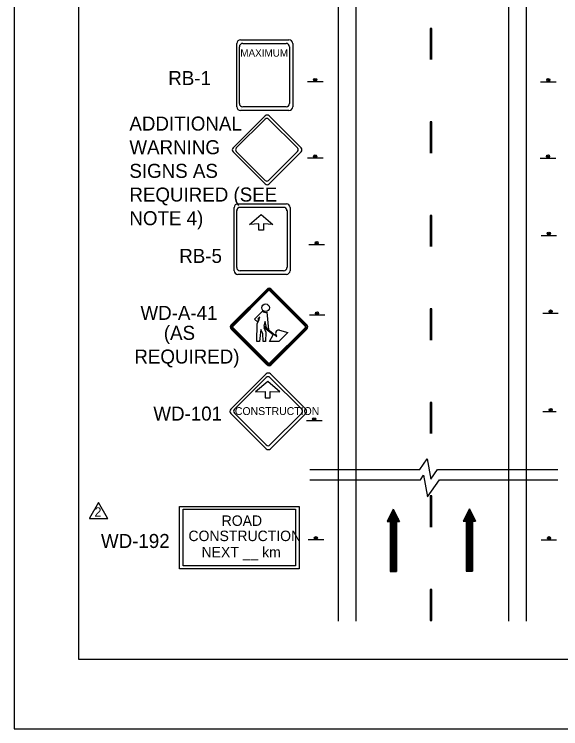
# Model space of a CAD drawing. Extents: x 1381 to 1597, y 125 to 404.
# Drawn here: x 1381.2 to 1466.1, y 124.9 to 235.9 of the extents above; entities that cross this region are included whole.
import ezdxf

# ---------------------------------------------------------------- set-up
doc = ezdxf.new("R2010")
doc.units = 0
for name, color, linetype in [('Level 1', 7, 'Continuous'), ('Level 10', 7, 'Continuous'), ('Level 2', 7, 'Continuous'), ('Level 44', 7, 'Continuous'), ('Level 60', 7, 'Continuous')]:
    doc.layers.add(name, color=color, linetype=linetype)

msp = doc.modelspace()

# ---------------------------------------------------------------- linework, layer by layer
at = {"layer": 'Level 1'}
for p, q in [((1420.46, 193.21), (1414.88, 187.63)), ((1420.58, 193.08), (1415, 187.51)), ((1426.54, 187.51), (1420.96, 193.08)), ((1426.66, 187.63), (1421.09, 193.21)), ((1420.71, 192.96), (1415.13, 187.39)), ((1426.41, 187.38), (1420.84, 192.96)), ((1420.51, 190.76), (1420.5, 190.76)), ((1414.88, 187), (1420.45, 181.43)), ((1415, 187.13), (1420.58, 181.56)), ((1415.13, 187.25), (1420.7, 181.68)), ((1420.84, 181.68), (1426.41, 187.25)), ((1420.96, 181.56), (1426.54, 187.13)), ((1421.08, 181.43), (1426.66, 187))]:
    msp.add_line(p, q, dxfattribs=at)
for points in [[(1419.05, 188.56), (1419.19, 188.44), (1419.03, 188.04), (1418.52, 188.52), (1419.74, 189.77)], [(1419.05, 188.56), (1419.19, 188.44), (1419.03, 188.04), (1418.52, 188.52), (1419.74, 189.77)], [(1419.47, 186.95), (1419.29, 185.05), (1418.86, 185.05), (1418.92, 187.78), (1419.03, 188.04), (1418.52, 188.52), (1419.74, 189.77)], [(1422.41, 186.83), (1423.69, 186.44), (1422.3, 185.05), (1420.84, 185.05), (1421.39, 186.1), (1419.98, 187.26), (1420.25, 186.52), (1420.22, 185.05), (1419.87, 185.05), (1419.81, 186.31), (1419.47, 186.95), (1419.29, 185.05), (1418.86, 185.05), (1418.92, 187.78), (1419.36, 188.88), (1419.05, 188.56)], [(1422.41, 186.83), (1423.69, 186.44), (1422.3, 185.05), (1420.84, 185.05), (1421.39, 186.1), (1419.98, 187.26), (1420.25, 186.52), (1420.22, 185.05), (1419.87, 185.05), (1419.81, 186.31), (1419.47, 186.95), (1419.29, 185.05), (1418.86, 185.05), (1418.92, 187.78), (1419.36, 188.88), (1419.05, 188.56)], [(1420.43, 189.6), (1420.71, 186.88), (1420.35, 187.18), (1420.15, 188.19), (1419.98, 187.48), (1421.96, 185.84), (1421.83, 186.2)], [(1420.43, 189.6), (1420.71, 186.88), (1420.35, 187.18), (1420.15, 188.19), (1419.98, 187.48), (1421.96, 185.84), (1421.83, 186.2)], [(1420.43, 189.6), (1420.71, 186.88), (1421.96, 185.84), (1421.83, 186.2)], [(1422.41, 186.83), (1423.69, 186.44), (1422.3, 185.05), (1420.84, 185.05), (1421.39, 186.1), (1419.98, 187.26), (1420.25, 186.52), (1420.22, 185.05), (1419.87, 185.05), (1419.81, 186.31), (1419.47, 186.95)]]:
    msp.add_lwpolyline(points, dxfattribs=at)
for points in [[(1419.05, 188.56), (1419.19, 188.44), (1419.36, 188.88)], [(1420.35, 187.17), (1420.15, 188.19), (1419.98, 187.48)]]:
    msp.add_lwpolyline(points, close=True, dxfattribs=at)
msp.add_circle((1420.24, 190.31), 0.591, dxfattribs=at)
msp.add_circle((1420.24, 190.31), 0.591, dxfattribs=at)
msp.add_circle((1420.24, 190.31), 0.591, dxfattribs=at)
for centre, radius, start, end in [((1420.77, 192.89), 0.446, 45, 134.9651), ((1420.77, 192.89), 0.27, 45, 134.9651), ((1420.77, 192.89), 0.0948, 45, 134.9651), ((1420.24, 190.31), 0.734, 226.3135, 284.9576), ((1420.24, 190.31), 0.734, 226.3135, 284.9576), ((1420.24, 190.31), 0.734, 226.3135, 284.9576), ((1415.19, 187.32), 0.446, 134.965, 225), ((1415.19, 187.32), 0.27, 134.965, 225), ((1426.35, 187.32), 0.27, 314.9651, 45), ((1426.35, 187.32), 0.446, 314.9651, 45), ((1415.19, 187.32), 0.0948, 134.965, 225), ((1422.27, 186.37), 0.475, 73.381, 201.0999), ((1422.27, 186.37), 0.475, 73.381, 201.0999), ((1422.27, 186.37), 0.475, 73.381, 201.0999), ((1426.35, 187.32), 0.0948, 314.9651, 45), ((1420.77, 181.75), 0.446, 225, 314.9652), ((1420.77, 181.75), 0.27, 225, 314.9652), ((1420.77, 181.75), 0.0948, 225, 314.9652)]:
    msp.add_arc(centre, radius, start, end, dxfattribs=at)
at = {"layer": 'Level 10'}
for p, q in [((1434.3, 141.65), (1434.3, 387.59)), ((1458.01, 141.65), (1458.01, 387.59)), ((1460.73, 387.59), (1460.73, 141.65)), ((1431.55, 141.65), (1431.55, 334.55)), ((1440.08, 159.02), (1439.11, 157.09)), ((1439.96, 158.78), (1439.96, 149.34)), ((1440.08, 159.02), (1440.08, 149.34)), ((1440.08, 159.02), (1441.05, 157.09)), ((1440.2, 158.78), (1440.2, 149.34)), ((1451.9, 159.07), (1450.93, 157.14)), ((1451.78, 158.83), (1451.78, 149.4)), ((1451.9, 159.07), (1451.9, 149.4)), ((1451.9, 159.07), (1452.86, 157.14)), ((1452.02, 158.83), (1452.02, 149.4)), ((1439.36, 157.57), (1439.36, 157.09)), ((1439.48, 157.81), (1439.48, 157.09)), ((1439.6, 158.06), (1439.6, 149.34)), ((1439.72, 158.3), (1439.72, 149.34)), ((1439.84, 158.54), (1439.84, 149.34)), ((1440.32, 158.54), (1440.32, 149.34)), ((1440.44, 158.3), (1440.44, 149.34)), ((1440.57, 158.06), (1440.57, 149.34)), ((1440.68, 157.81), (1440.68, 157.09)), ((1440.81, 157.57), (1440.81, 157.09)), ((1451.17, 157.62), (1451.17, 157.14)), ((1451.29, 157.86), (1451.29, 157.14)), ((1451.41, 158.11), (1451.41, 149.4)), ((1451.53, 158.35), (1451.53, 149.4)), ((1451.65, 158.59), (1451.65, 149.4)), ((1452.14, 158.59), (1452.14, 149.4)), ((1452.26, 158.35), (1452.26, 149.4)), ((1452.38, 158.11), (1452.38, 149.4)), ((1452.5, 157.86), (1452.5, 157.14)), ((1452.62, 157.62), (1452.62, 157.14)), ((1439.11, 157.09), (1439.6, 157.09)), ((1439.23, 157.33), (1439.23, 157.09)), ((1439.6, 157.09), (1439.6, 149.34)), ((1440.57, 157.09), (1440.57, 149.34)), ((1440.57, 157.09), (1441.05, 157.09)), ((1440.93, 157.33), (1440.93, 157.09)), ((1450.93, 157.14), (1451.41, 157.14)), ((1451.05, 157.38), (1451.05, 157.14)), ((1451.41, 157.14), (1451.41, 149.4)), ((1452.38, 157.14), (1452.38, 149.4)), ((1452.38, 157.14), (1452.86, 157.14)), ((1452.74, 157.38), (1452.74, 157.14)), ((1439.6, 149.34), (1440.57, 149.34)), ((1451.41, 149.4), (1452.38, 149.4))]:
    msp.add_line(p, q, dxfattribs=at)
at = {"layer": 'Level 2'}
for p, q in [((1445.8, 233.66), (1445.8, 228.83)), ((1446.09, 233.66), (1445.8, 233.66)), ((1446.09, 228.83), (1446.09, 233.66)), ((1445.8, 219.15), (1445.8, 214.31)), ((1446.09, 219.15), (1445.8, 219.15)), ((1446.09, 214.31), (1446.09, 219.15)), ((1445.8, 204.64), (1445.8, 199.8)), ((1446.09, 204.64), (1445.8, 204.64)), ((1446.09, 199.8), (1446.09, 204.64)), ((1445.8, 190.12), (1445.8, 185.28)), ((1446.09, 190.12), (1445.8, 190.12)), ((1446.09, 185.28), (1446.09, 190.12)), ((1445.8, 175.61), (1445.8, 170.77)), ((1446.09, 175.61), (1445.8, 175.61)), ((1446.09, 170.77), (1446.09, 175.61)), ((1445.8, 161.09), (1445.8, 156.26)), ((1446.09, 161.09), (1445.8, 161.09)), ((1446.09, 156.26), (1446.09, 161.09)), ((1445.8, 146.58), (1445.8, 141.74)), ((1446.09, 146.58), (1445.8, 146.58)), ((1446.09, 141.74), (1446.09, 146.58)), ((1445.8, 141.74), (1446.09, 141.74))]:
    msp.add_line(p, q, dxfattribs=at)
for points in [[(1406.85, 159.43), (1425.47, 159.43), (1425.47, 149.77), (1406.85, 149.77)], [(1407.43, 159.05), (1424.86, 159.05), (1424.86, 150.24), (1407.43, 150.24)]]:
    msp.add_lwpolyline(points, close=True, dxfattribs=at)
at = {"layer": 'Level 44'}
for p, q in [((1416.35, 231.89), (1423.87, 231.89)), ((1415.77, 221.52), (1415.77, 231.31)), ((1416.16, 222.01), (1416.16, 230.83)), ((1416.68, 231.35), (1423.44, 231.35)), ((1423.97, 230.83), (1423.97, 222.01)), ((1424.45, 231.31), (1424.45, 221.52)), ((1429.16, 225.4), (1426.74, 225.4)), ((1429.16, 225.4), (1426.74, 225.4)), ((1462.95, 225.4), (1465.37, 225.4)), ((1416.16, 222.01), (1416.16, 222.01)), ((1415.77, 221.51), (1415.77, 221.52)), ((1423.87, 220.93), (1416.35, 220.93)), ((1416.48, 221.17), (1416.48, 221.17)), ((1423.44, 221.49), (1416.68, 221.49)), ((1420.18, 220.1), (1415.19, 215.11)), ((1425.76, 215.11), (1420.77, 220.1)), ((1415.68, 215.11), (1420.18, 219.6)), ((1420.71, 219.6), (1425.2, 215.11)), ((1415.19, 214.52), (1420.18, 209.53)), ((1415.19, 214.52), (1415.19, 214.52)), ((1420.18, 210.08), (1415.68, 214.58)), ((1425.2, 214.58), (1420.71, 210.08)), ((1420.77, 209.53), (1425.76, 214.52)), ((1429.16, 213.54), (1426.74, 213.54)), ((1429.16, 213.54), (1426.74, 213.54)), ((1462.91, 213.53), (1465.33, 213.53)), ((1415.94, 206.44), (1423.46, 206.44)), ((1415.36, 196.06), (1415.36, 205.86)), ((1415.75, 196.56), (1415.75, 205.38)), ((1416.27, 205.9), (1423.04, 205.9)), ((1423.56, 205.38), (1423.56, 196.56)), ((1424.04, 205.86), (1424.04, 196.06)), ((1463.03, 201.54), (1465.45, 201.54)), ((1463.03, 201.54), (1465.45, 201.54)), ((1429.39, 200.07), (1426.97, 200.07)), ((1429.39, 200.07), (1426.97, 200.07)), ((1415.75, 196.55), (1415.75, 196.56)), ((1415.36, 196.06), (1415.36, 196.06)), ((1423.46, 195.48), (1415.94, 195.48)), ((1423.04, 196.03), (1416.27, 196.03)), ((1429.44, 189.15), (1427.03, 189.15)), ((1463.3, 189.46), (1465.72, 189.46)), ((1420.33, 180.03), (1414.84, 174.54)), ((1426.46, 174.54), (1420.98, 180.03)), ((1415.39, 174.53), (1420.33, 179.47)), ((1420.57, 178.83), (1418.68, 177.23)), ((1422.46, 177.23), (1420.57, 178.83)), ((1420.91, 179.47), (1425.85, 174.53)), ((1418.68, 177.23), (1420.19, 177.31)), ((1420.19, 177.31), (1420.19, 176.31)), ((1420.95, 176.31), (1420.95, 177.31)), ((1420.95, 177.31), (1422.46, 177.23)), ((1420.19, 176.31), (1420.94, 176.31)), ((1463.33, 174.17), (1465.4, 174.17)), ((1414.84, 173.89), (1420.33, 168.4)), ((1414.84, 173.89), (1414.84, 173.89)), ((1420.33, 169.01), (1415.39, 173.95)), ((1425.85, 173.95), (1420.91, 169.01)), ((1420.98, 168.4), (1426.46, 173.89)), ((1429, 172.72), (1426.58, 172.72)), ((1429, 172.72), (1426.58, 172.72)), ((1444.19, 165.21), (1445.33, 166.82)), ((1445.33, 166.82), (1445.89, 163.7)), ((1427.1, 165.21), (1444.19, 165.21)), ((1444.28, 163.59), (1444.78, 164.29)), ((1444.78, 164.29), (1445.37, 160.93)), ((1445.89, 163.7), (1446.95, 165.21)), ((1446.95, 165.21), (1465.66, 165.21)), ((1427.1, 163.59), (1444.28, 163.59)), ((1445.37, 160.93), (1447.25, 163.59)), ((1447.25, 163.59), (1465.66, 163.59)), ((1429.26, 154.25), (1426.84, 154.25)), ((1429.26, 154.25), (1426.84, 154.25)), ((1429.26, 154.25), (1426.84, 154.25)), ((1429.26, 154.25), (1426.84, 154.25)), ((1463.04, 154.25), (1465.46, 154.25))]:
    msp.add_line(p, q, dxfattribs=at)
msp.add_lwpolyline([(1417.73, 203.23), (1419.55, 204.76), (1421.36, 203.23), (1419.91, 203.31), (1419.91, 202.34), (1419.19, 202.34), (1419.19, 203.31)], close=True, dxfattribs=at)
for centre, radius in [((1427.94, 225.67), 0.242), ((1427.94, 225.67), 0.242), ((1427.94, 225.67), 0.121), ((1427.94, 225.67), 0.121), ((1464.16, 225.67), 0.242), ((1464.16, 225.67), 0.121), ((1427.94, 213.81), 0.242), ((1427.94, 213.81), 0.242), ((1427.94, 213.81), 0.121), ((1427.94, 213.81), 0.121), ((1464.12, 213.8), 0.242), ((1464.12, 213.8), 0.121), ((1464.24, 201.81), 0.242), ((1464.24, 201.81), 0.242), ((1464.24, 201.81), 0.121), ((1464.24, 201.81), 0.121), ((1428.18, 200.34), 0.242), ((1428.18, 200.34), 0.242), ((1428.18, 200.34), 0.121), ((1428.18, 200.34), 0.121), ((1464.52, 189.73), 0.242), ((1464.52, 189.73), 0.121), ((1428.23, 189.42), 0.242), ((1428.23, 189.42), 0.121), ((1464.54, 174.44), 0.242), ((1464.54, 174.44), 0.121), ((1427.78, 172.99), 0.242), ((1427.78, 172.99), 0.242), ((1427.78, 172.99), 0.121), ((1427.78, 172.99), 0.121), ((1428.04, 154.52), 0.242), ((1428.04, 154.52), 0.242), ((1428.04, 154.52), 0.242), ((1428.04, 154.52), 0.242), ((1428.04, 154.52), 0.121), ((1428.04, 154.52), 0.121), ((1428.04, 154.52), 0.121), ((1428.04, 154.52), 0.121), ((1464.26, 154.52), 0.242), ((1464.26, 154.52), 0.121)]:
    msp.add_circle(centre, radius, dxfattribs=at)
for centre, radius, start, end in [((1416.35, 231.31), 0.58, 90, 180), ((1423.87, 231.31), 0.58, 360, 90), ((1416.68, 230.83), 0.522, 90, 180), ((1423.44, 230.83), 0.522, 360, 90), ((1416.68, 222.01), 0.522, 180, 270), ((1423.44, 222.01), 0.522, 270, 360), ((1416.35, 221.51), 0.58, 180, 270), ((1423.87, 221.51), 0.58, 270, 360), ((1420.47, 219.81), 0.418, 45, 135), ((1420.44, 219.33), 0.376, 45, 135), ((1415.48, 214.82), 0.418, 135, 225), ((1415.95, 214.84), 0.376, 135, 225), ((1424.93, 214.84), 0.376, 315, 45), ((1425.46, 214.82), 0.418, 315, 45), ((1420.44, 210.35), 0.376, 225, 315), ((1420.47, 209.83), 0.418, 225, 315), ((1415.94, 205.86), 0.58, 90, 180), ((1423.46, 205.86), 0.58, 360, 90), ((1416.27, 205.37), 0.522, 90, 180), ((1423.03, 205.37), 0.522, 360, 90), ((1416.27, 196.55), 0.522, 180, 270), ((1423.03, 196.55), 0.522, 270, 360), ((1415.94, 196.06), 0.58, 180, 270), ((1423.46, 196.06), 0.58, 270, 360), ((1420.65, 179.7), 0.459, 45, 135), ((1420.62, 179.18), 0.413, 45, 135), ((1415.16, 174.21), 0.459, 135, 225), ((1415.68, 174.24), 0.413, 135, 225), ((1425.56, 174.24), 0.413, 315, 45), ((1426.14, 174.21), 0.459, 315, 45), ((1420.62, 169.3), 0.413, 225, 315), ((1420.65, 168.73), 0.459, 225, 315)]:
    msp.add_arc(centre, radius, start, end, dxfattribs=at)
at = {"layer": 'Level 60'}
for p, q in [((1391.18, 135.75), (1391.18, 135.75)), ((1381.18, 124.94), (1381.18, 124.94))]:
    msp.add_line(p, q, dxfattribs=at)
for points in [[(1597.18, 403.94), (1381.18, 403.94), (1381.18, 124.94), (1597.18, 124.94)], [(1578.06, 393.13), (1391.18, 393.13), (1391.18, 135.75), (1578.06, 135.75)]]:
    msp.add_lwpolyline(points, close=True, dxfattribs=at)
for points in [[(1394.28, 160.07), (1392.89, 157.65)], [(1394.28, 160.07), (1392.89, 157.65)], [(1395.67, 157.65), (1394.28, 160.07)], [(1392.89, 157.65), (1392.86, 157.6), (1395.7, 157.6), (1395.67, 157.65)], [(1392.89, 157.65), (1392.86, 157.6), (1395.7, 157.6), (1395.67, 157.65)]]:
    msp.add_lwpolyline(points, dxfattribs=at)

# ---------------------------------------------------------------- texts
at = {"layer": 'Level 10'}
for s, height, p in [('RB-1', 2.178, (1405.11, 224.88)), ('ADDITIONAL', 2.177, (1399.07, 217.81)), ('WARNING', 2.177, (1399.07, 214.14)), ('SIGNS AS ', 2.177, (1399.07, 210.47)), ('REQUIRED (SEE ', 2.177, (1399.07, 206.79)), ('NOTE 4)', 2.177, (1399.07, 203.12)), ('RB-5', 2.177, (1406.82, 197.26)), ('WD-A-41', 2.177, (1400.79, 188.42)), ('WD-101', 2.177, (1402.79, 172.78))]:
    msp.add_text(s, height=height, rotation=360, dxfattribs=at).set_placement(p)
for s, p in [('(AS ', (1404.42, 185.32)), ('REQUIRED)', (1399.84, 181.64)), ('WD-192', (1394.65, 153))]:
    msp.add_text(s, height=2.177, dxfattribs=at).set_placement(p)
at = {"layer": 'Level 44'}
for s, height, p in [('MAXIMUM', 1.15, (1416.3, 229.29)), ('CONSTRUCTION', 1.2178, (1415.46, 173.65)), ('ROAD', 1.625, (1413.41, 156.43)), ('CONSTRUCTION', 1.625, (1408.25, 154.07))]:
    msp.add_text(s, height=height, rotation=360, dxfattribs=at).set_placement(p)
msp.add_text('NEXT __ km', height=1.625, dxfattribs=at).set_placement((1410.28, 151.54))
at = {"layer": 'Level 60'}
msp.add_text('2', height=1.45, rotation=360, dxfattribs=at).set_placement((1393.65, 157.87))
msp.add_text('2', height=1.45, rotation=360, dxfattribs=at).set_placement((1393.65, 157.87))

doc.saveas('drawing.dxf')
